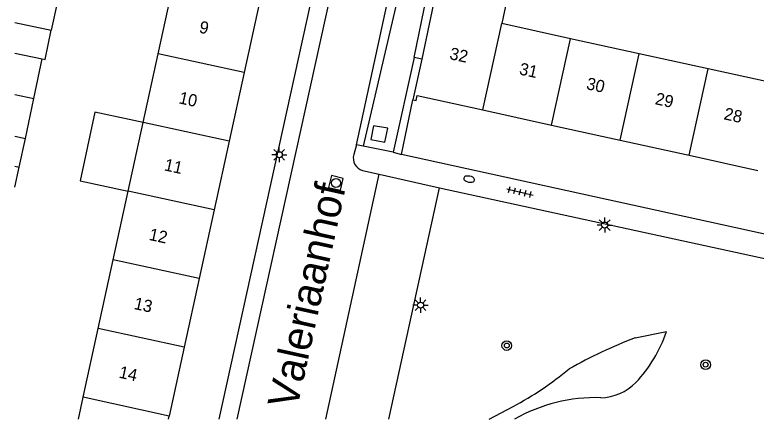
# Model space of a CAD drawing. Extents: x 130998 to 133001, y 398999 to 403002.
# Drawn here: x 131000 to 131061.1, y 399000 to 399033.3 of the extents above; entities that cross this region are included whole.
import ezdxf

# ---------------------------------------------------------------- set-up
doc = ezdxf.new("R2010")
doc.units = 0
for name, color, linetype in [('gg-anno-huisnummerreeks BGT', 7, 'Continuous'), ('gg-anno-openbare ruimte label', 7, 'Continuous'), ('gg-bbg-bijgebouw', 7, 'Continuous'), ('gg-bbg-gedigitaliseerde bebouwing', 7, 'Continuous'), ('gg-bbg-gedigitaliseerde bijgebouw', 7, 'Continuous'), ('gg-bbg-hoofdgebouw', 7, 'Continuous'), ('gg-bbg-luifel en loopbrug', 7, 'Continuous'), ('gg-bbg-tussenscheiding', 7, 'Continuous'), ('gg-knt-verharding', 7, 'Continuous'), ('gg-knt-verharding nz', 7, 'Continuous'), ('gg-kntw-greppel-droge sloot', 7, 'Continuous'), ('gg-kwrk-uitstroombak niveau min 01', 7, 'Continuous'), ('gt-grn-weggrens', 7, 'Continuous'), ('gt-symb-boom', 7, 'Continuous'), ('gt-symb-brandkraan', 7, 'Continuous'), ('gt-symb-lichtmast', 7, 'Continuous'), ('gt-symb-rioolschacht', 7, 'Continuous'), ('gt-symb-tegel verharding', 7, 'Continuous')]:
    doc.layers.add(name, color=color, linetype=linetype)

# ---------------------------------------------------------------- blocks, each defined once
blk = doc.blocks.new('gt0-BR')
at = {"layer": 'gt-symb-brandkraan'}
for centre, radius, start, end in [((-0.244, 0), 0.206, 107.56694, 252.43307), ((0.599, -2.664), 3, 106.89205, 107.56694), ((0, -0.691), 0.938, 73.10799, 106.89205), ((-0.599, -2.664), 3, 72.43309, 73.10799), ((0.244, 0), 0.206, 287.56695, 72.43309), ((0.599, 2.664), 3, 252.43307, 253.10797), ((0, 0.691), 0.938, 253.10797, 286.89206), ((-0.599, 2.664), 3, 286.89206, 287.56695)]:
    blk.add_arc(centre, radius, start, end, dxfattribs=at)
blk = doc.blocks.new('gt0-LMAST')
at = {"layer": 'gt-symb-lichtmast'}
for p, q in [((-0.005, 0.246), (-0.005, 0.621)), ((-0.182, 0.173), (-0.447, 0.438)), ((0.172, 0.173), (0.437, 0.438)), ((-0.255, -0.004), (-0.63, -0.004)), ((-0.182, -0.181), (-0.447, -0.446)), ((-0.005, -0.254), (-0.005, -0.629)), ((0.437, -0.446), (0.172, -0.181)), ((0.245, -0.004), (0.62, -0.004))]:
    blk.add_line(p, q, dxfattribs=at)
blk.add_circle((-0.005, -0.004), 0.25, dxfattribs=at)
blk = doc.blocks.new('gt0-BOOM')
at = {"layer": 'gt-symb-boom'}
for radius in [0.4, 0.2]:
    blk.add_circle((0, 0), radius, dxfattribs=at)
blk = doc.blocks.new('gt0-TEG1')
at = {"layer": 'gt-symb-tegel verharding'}
for p, q in [((-1.125, 0), (1.125, 0)), ((-0.9, -0.25), (-0.9, 0.25)), ((-0.45, -0.25), (-0.45, 0.25)), ((0, -0.25), (0, 0.25)), ((0.45, -0.25), (0.45, 0.25)), ((0.9, -0.25), (0.9, 0.25))]:
    blk.add_line(p, q, dxfattribs=at)
blk = doc.blocks.new('gt0-RS')
at = {"layer": 'gt-symb-rioolschacht'}
blk.add_lwpolyline([(-0.5, -0.5), (0.5, -0.5), (0.5, 0.5), (-0.5, 0.5)], close=True, dxfattribs=at)
blk.add_circle((0, 0), 0.375, dxfattribs=at)

msp = doc.modelspace()

# ---------------------------------------------------------------- linework, layer by layer
at = {"layer": 'gg-bbg-bijgebouw'}
msp.add_line((131000, 399030.131), (131002.264, 399029.651), dxfattribs=at)
for points in [[(131000.273, 399035.069), (131003.51, 399034.376), (131003.003, 399032.011)], [(131002.264, 399029.651), (131002.487, 399029.604), (131003.003, 399032.011)]]:
    msp.add_lwpolyline(points, dxfattribs=at)
at = {"layer": 'gg-bbg-gedigitaliseerde bebouwing'}
for p, q in [((131011.824, 399030.082), (131013.06, 399035.737)), ((131045.786, 399031.321), (131040.119, 399032.562)), ((131051.452, 399030.08), (131045.786, 399031.321)), ((131010.588, 399024.427), (131011.824, 399030.082)), ((131057.12, 399028.839), (131051.452, 399030.08)), ((131062.786, 399027.598), (131057.12, 399028.839)), ((131009.352, 399018.772), (131010.588, 399024.427)), ((131008.116, 399013.117), (131009.352, 399018.772)), ((131006.88, 399007.462), (131008.116, 399013.117)), ((131005.644, 399001.807), (131006.88, 399007.462)), ((131005.248, 399000), (131005.644, 399001.807))]:
    msp.add_line(p, q, dxfattribs=at)
msp.add_lwpolyline([(131034.781, 399034.16), (131035.436, 399037.137), (131040.85, 399035.978), (131040.119, 399032.562)], dxfattribs=at)
at = {"layer": 'gg-bbg-gedigitaliseerde bijgebouw'}
for p, q in [((131000, 399023.298), (131000.875, 399023.106)), ((131000.357, 399020.739), (131000.875, 399023.106)), ((131000, 399019.108), (131000.357, 399020.739))]:
    msp.add_line(p, q, dxfattribs=at)
at = {"layer": 'gg-bbg-hoofdgebouw'}
for p, q in [((131020.136, 399034.19), (131018.899, 399028.535)), ((131034.511, 399034.22), (131033.525, 399029.646)), ((131033.525, 399029.646), (131032.801, 399026.29)), ((131018.899, 399028.535), (131017.663, 399022.88)), ((131038.559, 399025.454), (131044.225, 399024.211)), ((131044.225, 399024.211), (131049.892, 399022.969)), ((131017.663, 399022.88), (131016.427, 399017.225)), ((131049.892, 399022.969), (131055.559, 399021.726)), ((131055.559, 399021.726), (131061.225, 399020.483)), ((131016.427, 399017.225), (131015.191, 399011.57)), ((131015.191, 399011.57), (131013.955, 399005.915)), ((131013.955, 399005.915), (131012.719, 399000.26)), ((131012.662, 399000), (131012.719, 399000.26))]:
    msp.add_line(p, q, dxfattribs=at)
msp.add_lwpolyline([(131032.801, 399026.29), (131033.061, 399026.23), (131033.151, 399026.64), (131038.559, 399025.454)], dxfattribs=at)
at = {"layer": 'gg-bbg-luifel en loopbrug'}
for p, q in [((131001.571, 399026.389), (131002.264, 399029.651)), ((131000, 399026.722), (131001.571, 399026.389)), ((131000.875, 399023.106), (131001.571, 399026.389))]:
    msp.add_line(p, q, dxfattribs=at)
msp.add_lwpolyline([(131010.588, 399024.427), (131006.587, 399025.276), (131005.385, 399019.614), (131009.352, 399018.772)], dxfattribs=at)
at = {"layer": 'gg-bbg-tussenscheiding'}
for p, q in [((131000, 399032.668), (131003.003, 399032.011)), ((131038.559, 399025.454), (131040.119, 399032.562)), ((131044.225, 399024.211), (131045.786, 399031.321)), ((131018.899, 399028.535), (131011.824, 399030.082)), ((131049.892, 399022.969), (131051.452, 399030.08)), ((131055.559, 399021.726), (131057.12, 399028.839)), ((131017.663, 399022.88), (131010.588, 399024.427)), ((131000, 399020.817), (131000.357, 399020.739)), ((131016.427, 399017.225), (131009.352, 399018.772)), ((131015.191, 399011.57), (131008.116, 399013.117)), ((131013.955, 399005.915), (131006.88, 399007.462)), ((131012.719, 399000.26), (131005.644, 399001.807))]:
    msp.add_line(p, q, dxfattribs=at)
at = {"layer": 'gg-knt-verharding'}
for p, q in [((131018.332, 399000), (131032.328, 399063.578)), ((131028.142, 399022.596), (131032.649, 399043.215)), ((131032.897, 399029.784), (131031.188, 399021.97)), ((131033.525, 399029.646), (131032.897, 399029.784)), ((131031.855, 399021.785), (131032.801, 399026.29)), ((131028.142, 399022.596), (131027.922, 399021.775)), ((131028.712, 399022.479), (131028.142, 399022.596)), ((131031.188, 399021.97), (131028.712, 399022.479)), ((131065.786, 399014.345), (131031.855, 399021.785)), ((131028.66, 399020.471), (131030.033, 399020.159)), ((131030.033, 399020.159), (131034.988, 399019.057)), ((131030.805, 399000), (131034.988, 399019.057)), ((131034.988, 399019.057), (131064.486, 399012.625))]:
    msp.add_line(p, q, dxfattribs=at)
msp.add_lwpolyline([(131025.165, 399044.965), (131026.648, 399044.658), (131016.82, 399000)], dxfattribs=at)
msp.add_arc((131028.955, 399021.499), 1.069, 165.04013, 253.97533, dxfattribs=at)
at = {"layer": 'gg-knt-verharding nz'}
msp.add_line((131025.627, 399000), (131030.033, 399020.159), dxfattribs=at)
at = {"layer": 'gg-kntw-greppel-droge sloot'}
for p, q in [((131032.986, 399040.886), (131028.712, 399022.479)), ((131032.897, 399029.784), (131035.121, 399040.414)), ((131051.108, 399006.702), (131053.697, 399007.203)), ((131039.084, 399000), (131041.068, 399001.051))]:
    msp.add_line(p, q, dxfattribs=at)
for centre, radius, start, end in [((131042.816, 399010.901), 11.492, 316.6444, 341.23131), ((131068.406, 398962.898), 47.096, 111.54893, 118.87157), ((131028.59, 399024.591), 26.642, 297.92673, 309.86077), ((131048.199, 399005.933), 4.169, 271.04921, 315.49588), ((131047.844, 398988.345), 13.427, 88.16249, 119.76939)]:
    msp.add_arc(centre, radius, start, end, dxfattribs=at)
at = {"layer": 'gg-kwrk-uitstroombak niveau min 01'}
msp.add_lwpolyline([(131029.344, 399023.012), (131030.496, 399022.807), (131030.731, 399023.95), (131029.548, 399024.16), (131029.344, 399023.012)], dxfattribs=at)
at = {"layer": 'gt-grn-weggrens'}
msp.add_line((131031.188, 399021.97), (131031.855, 399021.785), dxfattribs=at)

# ---------------------------------------------------------------- block references
at = {"layer": 'gt-symb-boom'}
for p in [(131040.537, 399006.059), (131056.92, 399004.485)]:
    msp.add_blockref('gt0-BOOM', p, dxfattribs=at)
at = {"layer": 'gt-symb-brandkraan', "rotation": 168.77553158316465}
msp.add_blockref('gt0-BR', (131037.436, 399019.759), dxfattribs=at)
at = {"layer": 'gt-symb-lichtmast'}
for p in [(131021.796, 399021.773), (131048.609, 399015.984), (131033.437, 399009.389)]:
    msp.add_blockref('gt0-LMAST', p, dxfattribs=at)
at = {"layer": 'gt-symb-rioolschacht', "rotation": 76.37870914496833}
msp.add_blockref('gt0-RS', (131026.459, 399019.449), dxfattribs=at)
at = {"layer": 'gt-symb-tegel verharding', "rotation": -13.480126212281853}
msp.add_blockref('gt0-TEG1', (131041.626, 399018.704), dxfattribs=at)

# ---------------------------------------------------------------- texts
at = {"layer": 'gg-anno-huisnummerreeks BGT'}
for s, p in [('9', (131015.129, 399031.835)), ('32', (131035.764, 399029.651)), ('31', (131041.505, 399028.392)), ('30', (131047.032, 399027.18)), ('10', (131013.457, 399026.009)), ('29', (131052.699, 399025.937)), ('28', (131058.366, 399024.694)), ('11', (131012.251, 399020.494)), ('12', (131010.999, 399014.766)), ('13', (131009.757, 399009.08)), ('14', (131008.521, 399003.425))]:
    msp.add_text(s, height=1, rotation=347.6, dxfattribs=at).set_placement(p)
at = {"layer": 'gg-anno-openbare ruimte label'}
msp.add_text('Valeriaanhof', height=2.5, rotation=77.6, dxfattribs=at).set_placement((131023.249, 399000.751))

doc.saveas('drawing.dxf')
